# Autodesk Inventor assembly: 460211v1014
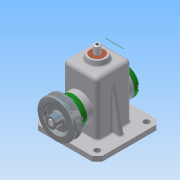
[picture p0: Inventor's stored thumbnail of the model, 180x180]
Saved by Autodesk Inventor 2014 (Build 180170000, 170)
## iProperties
Created: 2016-02
Part Number: 460211v1014
Document SubType Name: Assembly
Designer: User
Author: User
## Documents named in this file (15)
- C:\Documents and Settings\User\My Documents\Inventor\460211V1014\460211v1014.iam
- C:\Documents and Settings\User\My Documents\Inventor\460211V1014\본체.ipt
- C:\Documents and Settings\User\My Documents\Inventor\460211V1014\앞커버.ipt
- C:\Documents and Settings\User\My Documents\Inventor\460211V1014\뒤커버.ipt
- C:\Documents and Settings\User\My Documents\Inventor\460211V1014\편심축.ipt
- C:\Documents and Settings\User\My Documents\Inventor\460211V1014\베어링 12 x 32 x 10.ipt
- C:\Documents and Settings\User\My Documents\Inventor\460211V1014\오일실 12 25 7.ipt
- C:\Documents and Settings\User\My Documents\Inventor\460211V1014\키 4 x 4 x 10.ipt
- C:\Documents and Settings\User\My Documents\Inventor\460211V1014\V벨트풀리.ipt
- C:\Documents and Settings\User\My Documents\Inventor\460211V1014\링크.ipt
- C:\Documents and Settings\User\My Documents\Inventor\460211V1014\슬라이드.ipt
- C:\Documents and Settings\User\My Documents\Inventor\460211V1014\부시.ipt
- C:\Documents and Settings\User\My Documents\Inventor\460211V1014\볼트 M4 x 12.ipt
- C:\Documents and Settings\User\My Documents\Inventor\460211V1014\멈춤나사 M3x8.ipt
- C:\Documents and Settings\User\My Documents\Inventor\460211V1014\핀 5 x 18.ipt
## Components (10 placed, 3 different names)
1. V벨트풀리:1 — 플러쉬:2
2. 핀 5 x 18:1 — 각도:2
3. ISO 4762 M4 x 12:1
4. ISO 4762 M4 x 12:2
5. ISO 4762 M4 x 12:3
6. ISO 4762 M4 x 12:4
7. ISO 4762 M4 x 12:5
8. ISO 4762 M4 x 12:6
9. ISO 4762 M4 x 12:7
10. ISO 4762 M4 x 12:8
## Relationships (2: Flush 1, Angle 1)
- 플러쉬:2 [Flush]: V벨트풀리:1
- 각도:2 [Angle]: 핀 5 x 18:1
